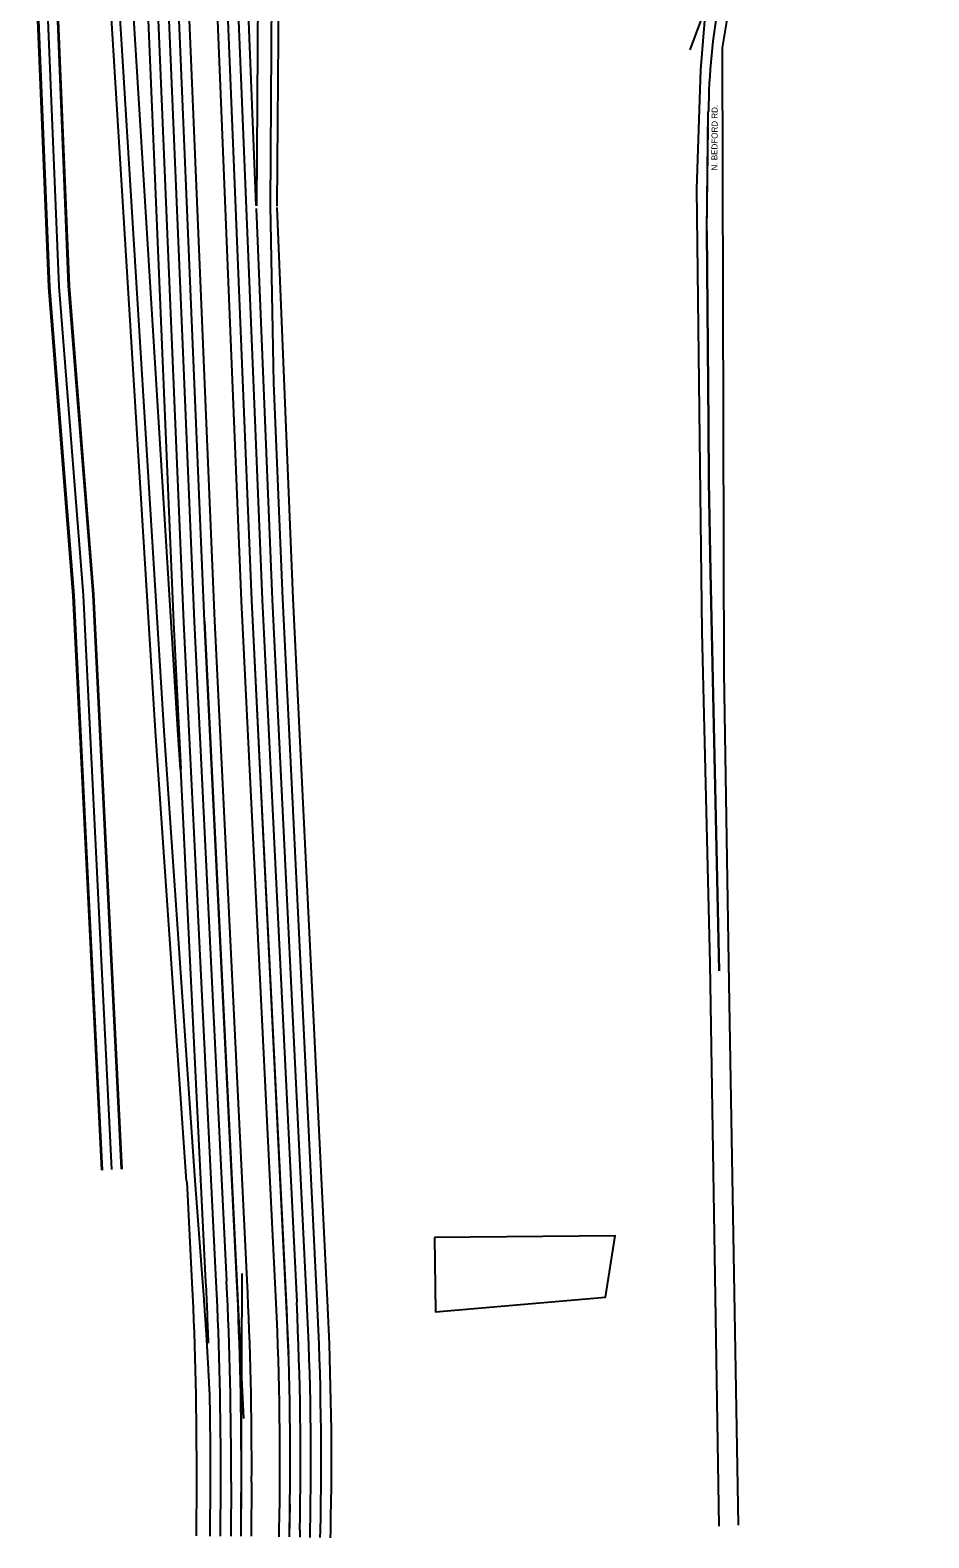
# Model space of a CAD drawing. Extents: x 227157 to 233208, y 434992 to 456232.
# Drawn here: x 229416 to 230462, y 434992 to 436747 of the extents above; entities that cross this region are included whole.
import ezdxf

# ---------------------------------------------------------------- set-up
doc = ezdxf.new("R2010")
doc.units = 0
for name, color, linetype in [('BD_X_Building', 7, 'Continuous'), ('Default', 7, 'Continuous'), ('GE_X_Alignment', 7, 'Continuous'), ('PM_X_Edge_Line', 7, 'Continuous'), ('PM_X_Lane_Line', 7, 'Continuous'), ('PV_X_EOP', 7, 'Continuous'), ('SV_X_Text_Name', 7, 'Continuous')]:
    doc.layers.add(name, color=color, linetype=linetype)

msp = doc.modelspace()

# ---------------------------------------------------------------- linework, layer by layer
at = {"layer": 'BD_X_Building'}
msp.add_lwpolyline([(229886.8, 435341.5), (229888, 435255), (230085.7, 435271.9), (230097.2, 435343.6)], close=True, dxfattribs=at)
at = {"layer": 'Default'}
msp.add_open_spline([(229625.1, 435155.7), (229625, 435158), (229624.8, 435162.4), (229624.5, 435169.1), (229624.1, 435175.8), (229623.8, 435182.5), (229623.4, 435189.2), (229623.1, 435195.8), (229622.7, 435202.5), (229622.3, 435209.2), (229621.9, 435215.9), (229621.5, 435222.6), (229621.1, 435229.2), (229620.7, 435235.9), (229620.2, 435242.6), (229619.8, 435249.3), (229619.3, 435255.9), (229618.9, 435262.6), (229618.4, 435269.3), (229617.9, 435275.9), (229617.4, 435282.6), (229617.1, 435287.1), (229616.9, 435289.3)], degree=3, dxfattribs=at)
at = {"layer": 'GE_X_Alignment'}
for p, q in [((229618.8, 436059.1), (229547.7, 437745.1)), ((229679.6, 436542.4), (229687.8, 437676.6)), ((230184.4, 436724.3), (230462.3, 437469.9)), ((229674.1, 436083.3), (229639.6, 436919.4)), ((229449.6, 436448.7), (229435.8, 436788.2)), ((230203.9, 436513.5), (230205.3, 436634.3)), ((230203.9, 436513.5), (230205.8, 436288)), ((230205.8, 436288), (230206.2, 436221.8)), ((230206.2, 436221.8), (230207.9, 436116)), ((230207.9, 436116), (230218.2, 435652.1)), ((229717.2, 435205.6), (229674.1, 436083.3)), ((229618.8, 436059.1), (229664.4, 435130.7)), ((229661.5, 434993.8), (229662.9, 435299.6)), ((229717.7, 434992.9), (229718.5, 435030.5))]:
    msp.add_line(p, q, dxfattribs=at)
for centre, radius, start, end in [((230965.4, 436643.8), 759.9, 159.5614, 179.3497), ((225293.3, 435076.7), 4368.5, 359.738, 2.8155), ((225989.1, 435082.9), 3729.6, 358.7454, 2.8094)]:
    msp.add_arc(centre, radius, start, end, dxfattribs=at)
at = {"layer": 'PM_X_Edge_Line'}
for p, q in [((229674.1, 436083.3), (229630.9, 437130.8)), ((229679.2, 436543.1), (229654.9, 437131.8)), ((229679.6, 436542.4), (229683.6, 437092.3)), ((229695.6, 436542.2), (229699.6, 437092.2)), ((229438.6, 436448), (229416.8, 436982.6)), ((229449.6, 436448.7), (229427.8, 436983)), ((229460.5, 436449.3), (229438.8, 436983.5)), ((229571.7, 435931.4), (229511, 436917.9)), ((229571.7, 435931.4), (229512.3, 436896)), ((229587.7, 435932.5), (229528.3, 436897)), ((229551.1, 436809.5), (229582.8, 436057.4)), ((229618.8, 436059.1), (229587.1, 436811.1)), ((230203.9, 436513.5), (230205.5, 436652.5)), ((229699.7, 436336.2), (229695.6, 436542.8)), ((230205.8, 436288), (230203.9, 436513.5)), ((229467.1, 436088.8), (229438.6, 436448)), ((229478.1, 436089.5), (229449.6, 436448.7)), ((229489.1, 436090.2), (229460.5, 436449.3)), ((229710.1, 436085), (229699.7, 436336.2)), ((230206.2, 436221.8), (230205.8, 436288)), ((230207.9, 436116), (230206.2, 436221.8)), ((230218.2, 435652.1), (230207.9, 436116)), ((229500.2, 435420), (229467.1, 436088.8)), ((229511.1, 435420.5), (229478.1, 436089.5)), ((229522.1, 435421.1), (229489.1, 436090.2)), ((229714.3, 435265.7), (229674.1, 436083.3)), ((229750.2, 435267.5), (229710.1, 436085)), ((229656.5, 435291.2), (229618.8, 436059.1)), ((229582.8, 436057.4), (229591.2, 435886.8)), ((229607.8, 435407.7), (229571.7, 435931.4)), ((229590.9, 435886.5), (229587.7, 435932.5)), ((229616.9, 435289.3), (229607.8, 435407.9)), ((229625.5, 434993.9), (229625.8, 435056.8)), ((229661.5, 434993.8), (229661.8, 435056.7)), ((229717.7, 434992.9), (229717.8, 435001.2)), ((229753.6, 434992.1), (229753.8, 435000.4))]:
    msp.add_line(p, q, dxfattribs=at)
for centre, radius, start, end in [((230965.4, 436643.8), 759.9, 159.5614, 179.3497), ((225293.3, 435076.7), 4368.5, 359.738, 2.8155), ((225989.1, 435082.9), 3729.6, 358.7454, 2.8094), ((225989.1, 435082.9), 3765.6, 358.7454, 2.8094), ((225293.3, 435076.7), 4332.5, 359.738, 1.0459)]:
    msp.add_arc(centre, radius, start, end, dxfattribs=at)
at = {"layer": 'PM_X_Lane_Line'}
for p, q in [((229642.9, 437131.3), (229686.1, 436083.9)), ((229594.8, 436058), (229563.1, 436810)), ((229575.1, 436810.5), (229606.8, 436058.5)), ((229698.1, 436084.4), (229679.3, 436539.3)), ((229686.1, 436083.9), (229726.2, 435266.3)), ((229738.2, 435266.9), (229698.1, 436084.4)), ((229606.8, 436058.5), (229644.5, 435290.6)), ((229632.6, 435290.1), (229594.8, 436058)), ((229620.6, 435289.5), (229591.2, 435886.7)), ((229637.5, 434993.9), (229637.8, 435056.8)), ((229649.8, 435056.7), (229649.5, 434993.8)), ((229729.8, 435001), (229729.7, 434992.6)), ((229741.7, 434992.4), (229741.8, 435000.7))]:
    msp.add_line(p, q, dxfattribs=at)
for centre, radius, start, end in [((225293.3, 435076.7), 4332.5, 1.8772, 2.8155), ((225293.3, 435076.7), 4344.5, 359.738, 2.8155), ((225293.3, 435076.7), 4356.5, 359.738, 2.8155), ((225989.1, 435082.9), 3741.6, 358.7454, 2.8094), ((225989.1, 435082.9), 3753.6, 358.7454, 2.8094)]:
    msp.add_arc(centre, radius, start, end, dxfattribs=at)
at = {"layer": 'PV_X_EOP'}
for p, q in [((229662.1, 436082.8), (229618.9, 437130.3)), ((229703.6, 436542.2), (229707.6, 437092.1)), ((229437.6, 436448), (229415.8, 436982.5)), ((229461.5, 436449.4), (229439.8, 436983.5)), ((229561.8, 435930.8), (229502.3, 436895.4)), ((229630.8, 436059.6), (229599, 436811.6)), ((229722.1, 436085.5), (229703.3, 436540.7)), ((229466.1, 436088.7), (229437.6, 436448)), ((229490.1, 436090.2), (229461.5, 436449.4)), ((229499.2, 435419.9), (229466.1, 436088.7)), ((229523.1, 435421.1), (229490.1, 436090.2)), ((229702.3, 435265.1), (229662.1, 436082.8)), ((229762.2, 435268.1), (229722.1, 436085.5)), ((229668.5, 435291.8), (229630.8, 436059.6)), ((229597.9, 435407.1), (229561.8, 435930.8)), ((229604.6, 435288.7), (229598.8, 435406.6)), ((229609.5, 434994), (229609.8, 435056.9)), ((229673.5, 434993.7), (229673.8, 435056.6)), ((229705.7, 434993.2), (229705.8, 435001.5)), ((229765.6, 434991.8), (229765.8, 435000.2))]:
    msp.add_line(p, q, dxfattribs=at)
for points in [[(230218.2, 435005.6), (230207.8, 435660.4), (230198.5, 436046.8), (230192.3, 436562.5), (230196.7, 436701), (230203.7, 436787), (230231.3, 436898.5)], [(230266.4, 436896.8), (230236.3, 436815.4), (230221.6, 436726.6), (230223.6, 435999.2), (230229.4, 435637.6), (230240.2, 435006.5)]]:
    msp.add_lwpolyline(points, dxfattribs=at)
for centre, radius, start, end in [((225293.3, 435076.7), 4316.5, 359.738, 2.8155), ((225293.3, 435076.7), 4380.5, 359.738, 2.8155), ((225989.1, 435082.9), 3717.6, 358.7454, 2.8094), ((225989.1, 435082.9), 3777.6, 358.7454, 2.8094)]:
    msp.add_arc(centre, radius, start, end, dxfattribs=at)

# ---------------------------------------------------------------- texts
at = {"layer": 'SV_X_Text_Name'}
msp.add_text('N. BEDFORD RD.', height=7, rotation=89.8444, dxfattribs=at).set_placement((230216.1, 436583.7))

doc.saveas('drawing.dxf')
